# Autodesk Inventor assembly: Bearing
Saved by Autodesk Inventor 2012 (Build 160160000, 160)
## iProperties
Created: 2010-12
Part Number: Bearing
Document SubType Name: Assembly
Designer: Beta-8540w
ClientObjectVersion: 1
Author: Beta-8540w
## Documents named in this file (2)
- C:\Users\VMuser\Desktop\Inventor 2012 Essentials\Assemblies\Chapter 8\Design Accelerators\Bearing c8-01.iam
- C:\Users\VMuser\Desktop\Inventor 2012 Essentials\Content Center Files\en-US\SKF NJ\SKF NJNJ 202 EC.ipt
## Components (1 placed, 1 different names)
1. SKF NJ SKF NJNJ 202 EC:1
